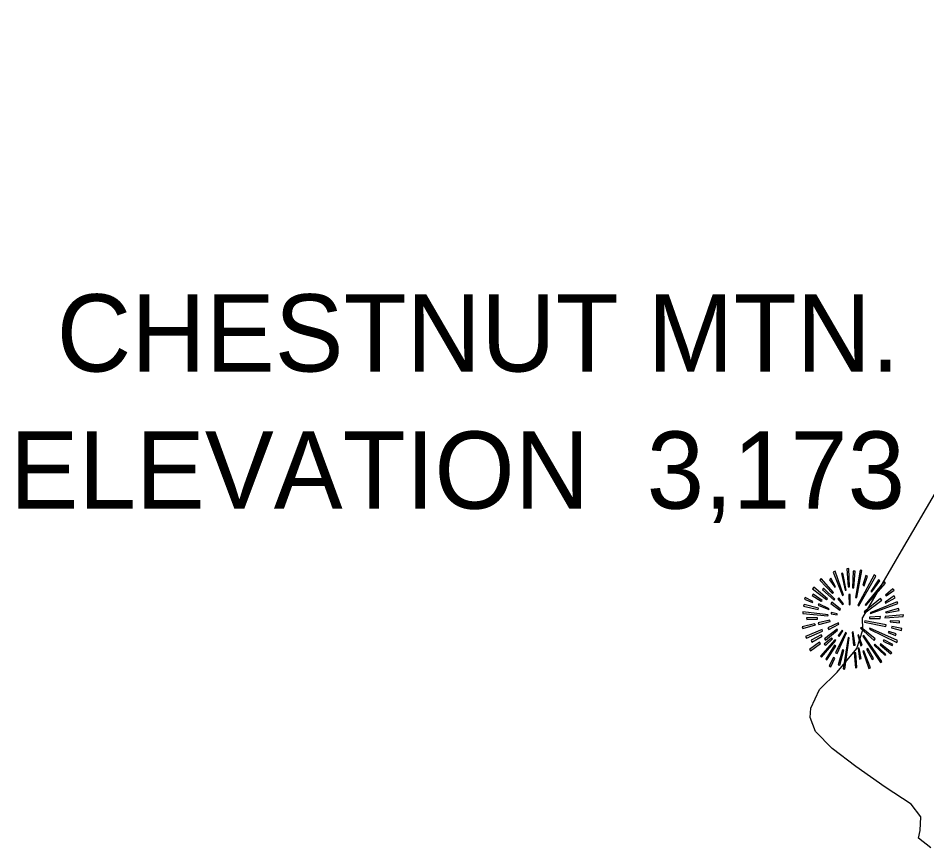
# Model space of a CAD drawing. Extents: x 1159738 to 1321356, y 736314 to 882035.
# Drawn here: x 1159738 to 1170094, y 814171 to 823625 of the extents above; entities that cross this region are included whole.
import ezdxf

# ---------------------------------------------------------------- set-up
doc = ezdxf.new("R2010")
doc.units = 0
for name, color, linetype in [('Exist Boundary Political CountyLine', 7, 'Continuous'), ('Exist Geographical Mountain Summit CELL', 7, 'Continuous'), ('Exist Geographical Mountain Summit Elevation Number Label', 7, 'Continuous'), ('Exist Geographical Mountain Summit Label', 7, 'Continuous')]:
    doc.layers.add(name, color=color, linetype=linetype)

msp = doc.modelspace()

# ---------------------------------------------------------------- linework, layer by layer
at = {"layer": 'Exist Boundary Political CountyLine'}
for points in [[(1180581, 836034), (1180196, 835393), (1178688, 832834), (1178315, 832211), (1177676, 831107), (1176400, 828855), (1175677, 827617), (1174443, 825496), (1172887, 822833), (1172185, 821634), (1171416, 820311), (1170628, 818973), (1170217, 818262), (1169800, 817555), (1169362, 816795)], [(1170141, 814171), (1169997, 814282), (1170018, 814370), (1170026, 814523), (1169915, 814670), (1169619, 814863), (1169286, 815100), (1169015, 815305), (1168825, 815496), (1168763, 815658), (1168770, 815764), (1168872, 815976), (1169070, 816173), (1169297, 816441), (1169366, 816656), (1169362, 816795)]]:
    msp.add_lwpolyline(points, dxfattribs=at)
at = {"layer": 'Exist Geographical Mountain Summit CELL'}
for points in [[(1169182, 817352), (1169198, 817144), (1169211, 817145), (1169205, 817356)], [(1169294, 817022), (1169354, 817330), (1169332, 817337), (1169281, 817025)], [(1168874, 817221), (1169018, 817071), (1169031, 817081), (1168890, 817240)], [(1168984, 817227), (1169047, 817140), (1169054, 817145), (1169000, 817243)], [(1169028, 817314), (1169133, 817047), (1169144, 817051), (1169048, 817324)], [(1169163, 817106), (1169173, 817109), (1169137, 817301), (1169120, 817296)], [(1169246, 817135), (1169262, 817135), (1169276, 817324), (1169255, 817324)], [(1169307, 816935), (1169319, 816927), (1169513, 817266), (1169492, 817281)], [(1169365, 817163), (1169378, 817158), (1169416, 817266), (1169397, 817273)], [(1169541, 817227), (1169457, 817093), (1169468, 817088), (1169558, 817214)], [(1168792, 817122), (1168951, 817000), (1168960, 817009), (1168807, 817140)], [(1168906, 817110), (1169037, 816994), (1169045, 817003), (1168917, 817131)], [(1169391, 816940), (1169400, 816932), (1169622, 817189), (1169606, 817208)], [(1168701, 817003), (1168791, 816968), (1168795, 816980), (1168707, 817023)], [(1168788, 817047), (1168891, 816981), (1168900, 816991), (1168800, 817062)], [(1169079, 817009), (1169134, 816943), (1169143, 816952), (1169092, 817020)], [(1169204, 817058), (1169209, 816942), (1169220, 816943), (1169220, 817059)], [(1169622, 816961), (1169733, 817020), (1169721, 817041), (1169617, 816971)], [(1169622, 817052), (1169630, 817042), (1169721, 817107), (1169707, 817122)], [(1168689, 816926), (1168855, 816888), (1168859, 816901), (1168694, 816945)], [(1168855, 816935), (1168977, 816887), (1168981, 816895), (1168864, 816951)], [(1169000, 816956), (1169101, 816881), (1169109, 816892), (1169010, 816969)], [(1169378, 816860), (1169386, 816850), (1169580, 816994), (1169567, 817012)], [(1169446, 816849), (1169451, 816840), (1169763, 816955), (1169756, 816974)], [(1168679, 816841), (1168967, 816814), (1168968, 816825), (1168679, 816862)], [(1169002, 816837), (1169070, 816828), (1169072, 816837), (1169005, 816854)], [(1169615, 816794), (1169825, 816807), (1169826, 816825), (1169617, 816807)], [(1169630, 816849), (1169777, 816875), (1169771, 816897), (1169624, 816858)], [(1168673, 816690), (1168679, 816670), (1168823, 816712), (1168814, 816725)], [(1168727, 816772), (1168846, 816778), (1168846, 816792), (1168723, 816792)], [(1168857, 816736), (1168861, 816717), (1168993, 816750), (1168990, 816765)], [(1168967, 816679), (1168976, 816660), (1169091, 816721), (1169086, 816734)], [(1169384, 816743), (1169627, 816695), (1169631, 816712), (1169388, 816757)], [(1169442, 816798), (1169442, 816786), (1169563, 816786), (1169566, 816807)], [(1169675, 816746), (1169781, 816737), (1169781, 816754), (1169676, 816758)], [(1168712, 816580), (1168723, 816561), (1168904, 816641), (1168899, 816660)], [(1168927, 816554), (1168939, 816539), (1169077, 816653), (1169070, 816663)], [(1169054, 816394), (1169072, 816387), (1169178, 816620), (1169168, 816624)], [(1169082, 816591), (1169095, 816580), (1169135, 816645), (1169128, 816651)], [(1169242, 816628), (1169258, 816480), (1169275, 816481), (1169255, 816631)], [(1169339, 816674), (1169493, 816533), (1169503, 816551), (1169346, 816683)], [(1169439, 816664), (1169752, 816511), (1169759, 816533), (1169445, 816676)], [(1169653, 816624), (1169737, 816591), (1169745, 816609), (1169659, 816636)], [(1169691, 816677), (1169804, 816648), (1169807, 816670), (1169695, 816695)], [(1168758, 816433), (1168769, 816417), (1168883, 816501), (1168872, 816514)], [(1168782, 816516), (1168899, 816583), (1168890, 816597), (1168774, 816536)], [(1168881, 816354), (1168893, 816344), (1169056, 816535), (1169044, 816543)], [(1168942, 816480), (1169019, 816552), (1169006, 816561), (1168925, 816493)], [(1169140, 816212), (1169159, 816208), (1169209, 816565), (1169197, 816568)], [(1169306, 816593), (1169340, 816474), (1169357, 816481), (1169314, 816597)], [(1169364, 816584), (1169566, 816285), (1169580, 816296), (1169374, 816589)], [(1169596, 816528), (1169697, 816475), (1169707, 816490), (1169605, 816543)], [(1169041, 816480), (1168941, 816323), (1168954, 816312), (1169057, 816471)], [(1169101, 816253), (1169149, 816424), (1169134, 816426), (1169083, 816257)], [(1169345, 816327), (1169323, 816446), (1169310, 816446), (1169328, 816323)], [(1169364, 816413), (1169434, 816213), (1169451, 816221), (1169375, 816416)], [(1169406, 816436), (1169470, 816318), (1169486, 816327), (1169421, 816442)], [(1169493, 816481), (1169614, 816365), (1169627, 816375), (1169502, 816491)], [(1169560, 816484), (1169682, 816381), (1169695, 816395), (1169567, 816494)], [(1168981, 816246), (1169000, 816234), (1169044, 816333), (1169031, 816341)], [(1169266, 816394), (1169281, 816224), (1169297, 816228), (1169284, 816394)]]:
    msp.add_lwpolyline(points, close=True, dxfattribs=at)

# ---------------------------------------------------------------- texts
at = {"layer": 'Exist Geographical Mountain Summit Elevation Number Label'}
msp.add_text('ELEVATION  3,173', height=880, dxfattribs=at).set_placement((1159642, 818036))
at = {"layer": 'Exist Geographical Mountain Summit Label'}
msp.add_text('CHESTNUT MTN.', height=880, dxfattribs=at).set_placement((1160177, 819599))

doc.saveas('drawing.dxf')
